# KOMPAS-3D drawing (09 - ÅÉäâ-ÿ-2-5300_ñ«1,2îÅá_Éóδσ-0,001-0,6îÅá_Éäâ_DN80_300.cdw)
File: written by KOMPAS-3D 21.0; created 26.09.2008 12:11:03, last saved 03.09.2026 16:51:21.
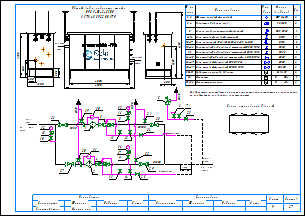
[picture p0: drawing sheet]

Sheets 1-2: A3, landscape

Document properties: Наименование: Макро:21; Автор: RaskoAdmin; Форматы листов документа: 2xA3; Полное имя файла: \\UR38nt01\Departments\КТО\КБ ПУРДГ\Заявки\Прайс-лист на типовые шкафы ГРПШ\ПРДГ_стандарт_20_03_2026\ПРДГ с РДГ(Н, В)\ПРДГ-Ш-2-5300_до1,2МПа_Рвых-0,001-0,6МПа_РДГ_DN80_300.cdw

Title block, sheet 1: Наименование: Пункт учета газа / ПУГ-Ш-400-Р / ЛГТИ.485922.001ТУ; designation: ЛГТИ.03.4411141; sheet number: 1; Количество листов документа: 2; organisation: ООО "ЭЛЬСТЕР Газэлектроника"; Форматы листов документа: A3; stored path: C:\Рабочие документы\Компас\ПУГ\Схема.cdw; Разработал: Устинов; Проверил: Кошкин; Утвердил: Кошкин
Title block, sheet 2: sheet number: 2; stored path: D:\Рабочие документы\Заявки\ПУРДГ\ПУРДГ-ШУЭО-2-100-Р 4411220.cdw; designation, second copy: ЛГТИ.03.4411141-

Views: Вид 1, Вид 2
Referenced files: wcvoit.frw
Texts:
  Normal
  № на
  схеме
  Усл.
  обозн.
  Марка
  (модель)
  Кол.
  Фильтр газовый фланцевый
  ФГ 16-80
  Регулятор давления газа
  РДГ-50
  Клапан предохранительный сбросной
  ПСК DN25
  Кран шаровой газовый латунный
  DN15
  Кран кнопочный VE-РАСКО-НЗ-1,6-G1/2-М20
  Кран шаровой "под приварку" штуцерный DN20 PN16
  Кран шаровой "под приварку" штуцерный DN25 PN16
  Кран шаровой "под приварку" штуцерный п/п DN20 PN16
  DN20
  DN25
  Кран шаровой фланцевый DN80 PN16
  Кран шаровой фланцевый DN300 PN16
  DN80
  DN300
  Индикатор перепада давления
  Delta 15
  Манометр
  Манометр-напоромер
  0...     МПа
  0...     кПа
  Общий вид и габариты шкафа
  ПРДГ-Ш-2-5300
  Выход газа
  Вход газа
  Схема открывания дверей
  logo-rasko-ge.png
  Предприятие изготовитель может заменять комплектующие на аналогичные,
  не ухудшающие заявленных характеристик.
  Вход
  газа
  PDI
  Выход
  Р=     кПа
  Импульс DN20
  ≥5DN
  HYSWLongFangSong
  Р=       МПа
  Должность
  Конструктор
  Фамилия
  Подпись
  Дата
  Согласовано
  Максимкин
  Лист
  Листов
  POLYLINE_STYLE_0.18_RGB_0_0_0
  POLYLINE_STYLE_0.50_RGB_0_0_0
  POLYLINE_STYLE_0.34_RGB_0_0_0
  PHANTOM_RGB_0_0_0_SC_1_THICK_0.18
  K5LT_THIN_RGB_0_0_0_THICK_0.18
  K5LT32769_RGB_0_0_0_THICK_0.18
  K5LT12_RGB_0_0_0_SC_1_THICK_0.18
  K5LT_DASHED_RGB_0_0_0_SC_1_THICK_0.18
  ACISOTGL_RGB_0_0_0_SC_0.8_THICK_0.25
  CONTINUOUS_RGB_0_127_31_THICK_0.3
  CONTINUOUS_RGB_0_0_255_THICK_0.35
  CONTINUOUS_RGB_255_0_0_THICK_0.35
  POLYLINE_STYLE_0.25_RGB_0_0_0
  CONTINUOUS_RGB_0_0_0_THICK_0.5
  POLYLINE_STYLE_0.35_RGB_0_0_255
  CONTINUOUS_RGB_0_0_0_THICK_0.4
  CONTINUOUS_RGB_0_0_0_THICK_0.35
  Без оформления
Dimensions and other numbers on the sheet: 1; 1, 2; 2; 3, 4; 5; 6-14; 9; 15-17; 3; 18-22; 23; 24-25; 26-27; 28-29; 30-31; 32; 33-34; 600; 1200; 500; 305; 2200; 4300; 1300; 4130; 4000; 4; 10; 27; 28; 29; 8; 12; 19; 20; 21; 22; 25; 24; 30; 31; 15; 16; 26; 6; 7; 11; 14; 13; 33; 17; 34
